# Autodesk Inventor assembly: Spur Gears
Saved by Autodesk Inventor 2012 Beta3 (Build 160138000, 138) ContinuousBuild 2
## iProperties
Created: 2010-12
Part Number: Spur Gears
Document SubType Name: Assembly
Designer: Thom Tremblay
Categories: <?xml version="1.0" encoding="UTF-16"?> <MemberInstance><Categories><FamilyTemplate/><ParamToTemplateMap><ParamToTemplate><ParamToTemplate CategoryParameter="//
ClientObjectVersion: 1
Author: Thom Tremblay
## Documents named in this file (1)
- C:\Inventor 2012 Essentials\Assemblies\Chapter 6\c6-01\Design Accelerator\Spur Gears4.iam
